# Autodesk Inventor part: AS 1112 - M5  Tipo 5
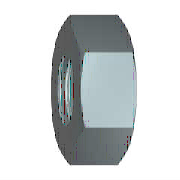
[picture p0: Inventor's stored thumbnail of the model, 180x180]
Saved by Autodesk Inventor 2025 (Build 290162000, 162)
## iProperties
Created: 2024-01
Part Number: AS 1112 - M5  Tipo 5
Material: Acciaio, Dolce
Description: Dadi esagonali metrici ISO, inclusi dadi sottili, dadi con intaglio e dadi a corona
Document SubType Name: Modeling
Standard: AS 1112
Designer: R5800u
Standards Organization: AS
Language: it-IT
Size Designation: M5  Tipo 5
Categories: <MemberInstance><Categories><Category DisplayName="Elementi di fissaggio" InternalName="e4da775c-781d-43d5-af7c-5136215cf5a6" Mnemonic="FSTN"><Category DisplayN
Density: 7.85 g/cm^3
Appearance: Semilucidato
IsCustomPart: 0
Author: R5800u
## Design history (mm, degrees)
body "Solid1"
workaxis "Work Axis1"
workplane "Work Plane1"
sketch "Schizzo1"
  geometry: L1 (-4.619, 0)-(-2.309, 4); L2 (-2.309, 4)-(2.309, 4); L3 (2.309, 4)-(4.619, 0); L4 (4.619, 0)-(2.309, -4); L5 (2.309, -4)-(-2.309, -4); L6 (-2.309, -4)-(-4.619, 0); 2 further points
  constraints: 12 end point, 1 coincident, 1 horizontal, 11 other
  dimensions: "d0" = 9.2376 distance of L3.end L1.start (= 1.1547 x SW)
extrude "Corpo" new body sketch "Schizzo1" distance "d1" = 4.7 (= KOH); taper "d2" = 0 deg
revolve "Smusso1" stored, may be unused: angle "d7" = 90 deg
sketch "Schizzo3"
  geometry: A1 r 4 centre (0, 0) between (-2, -3.464) and (2, -3.464) reference; 1 further point
  constraints: 1 coincident
hole "Filettatura" sketch "Schizzo3" diameter "d25" = 4.134; stored, may be unused: countersink angle "d29" = 82 deg, drill point angle "d31" = 118 deg; dims "d26" = 6, "d27" = 4, "d28" = 2, "d30" = 8
chamfer "Smusso2" distance "d8" = 0.43301 (= -0.5 x GD1 + 0.5 x NND); stored, may be unused: angle "d9" = 30 deg, second distance "d40" = 0.43301 (= -0.5 x GD1 + 0.5 x NND)
chamfer "Smusso3" distance "d10" = 0.43301 (= -0.5 x GD1 + 0.5 x NND); stored, may be unused: angle "d11" = 30 deg, second distance "d41" = 0.43301 (= -0.5 x GD1 + 0.5 x NND)
sketch "Schizzo2"
  geometry: L1 (0, 2.309)-(0, 4.619) reference; L2 (0, 4.619)-(4.7, 4.619) reference; L3 (4.7, 2.309)-(4.7, 4.619) reference; L4 (-0.94, 0)-(5.64, 0) reference; L5 (0.357, 4.619)-(0, 4); L6 (4.343, 4.619)-(4.7, 4)
  constraints: 4 end point, 4 point on line
  dimensions: "d3" = 30 deg angle of L1 L5 (= ANG1); "d4" = 30 deg angle of L3 L6 (= ANG2); "d5" = 8 diameter of L5.end L4 (= SW0); "d6" = 8 diameter of L6.end L4 (= SW01)
other parameters: "ANG1" = 30 deg [user parameter; used in 1 equation term], "ANG2" = 30 deg [user parameter; used in 1 equation term], "NND" = 5 [user parameter; used in 4 equation terms], "KOH" = 4.7 [user parameter; used in 1 equation term], "SW" = 8 [user parameter; used in 4 equation terms], "SW0" = 8 (= SW) [user parameter; used in 1 equation term], "SW01" = 8 (= SW) [user parameter; used in 1 equation term], "GD1" = 4.13397 (computed from THREADDIA, PTC, TOA) [user parameter; used in 4 equation terms], "d13" = 0, "d14" = 0, "d39" = 0, "d42" = 0, "GUL" = 0.43301 (= 0.541266 x PTC) [user parameter], "TPU" = 12.5 (computed from PTC) [user parameter], "WFT" = 0.5 [user parameter], "THREADDIA" = 5 [user parameter; used in 1 equation term], "TOA" = 30 deg [user parameter; used in 1 equation term], "PTC" = 0.8 [user parameter; used in 4 equation terms], "E0" = 9.24 (= 1.155 x SW) [user parameter], "GAL" = 0.43301 (= 0.541266 x PTC) [user parameter]
